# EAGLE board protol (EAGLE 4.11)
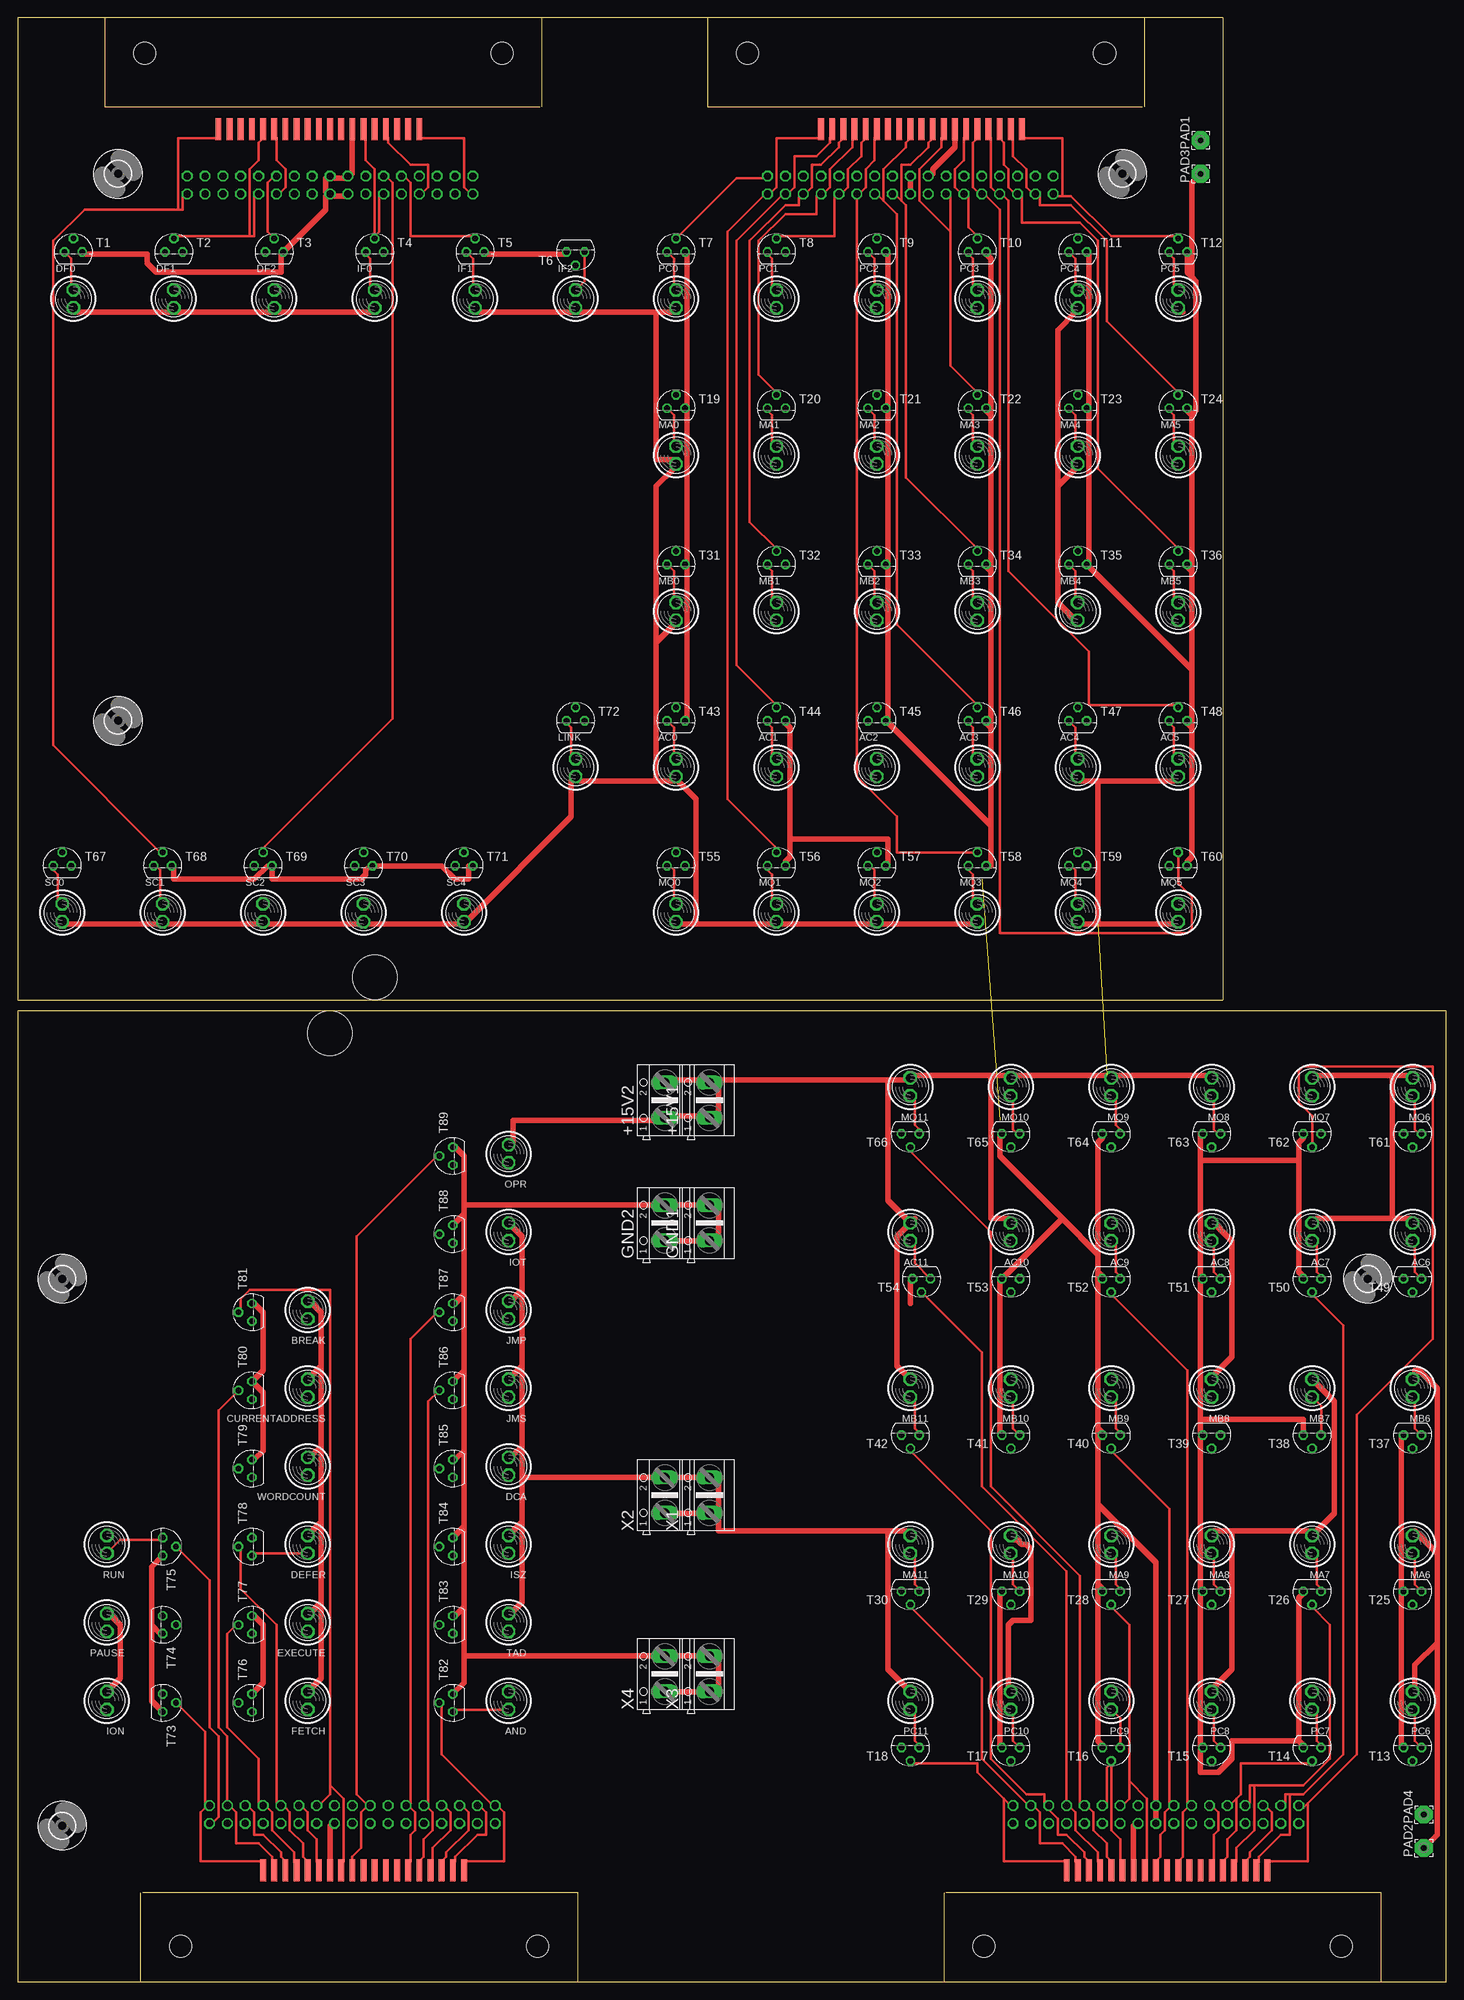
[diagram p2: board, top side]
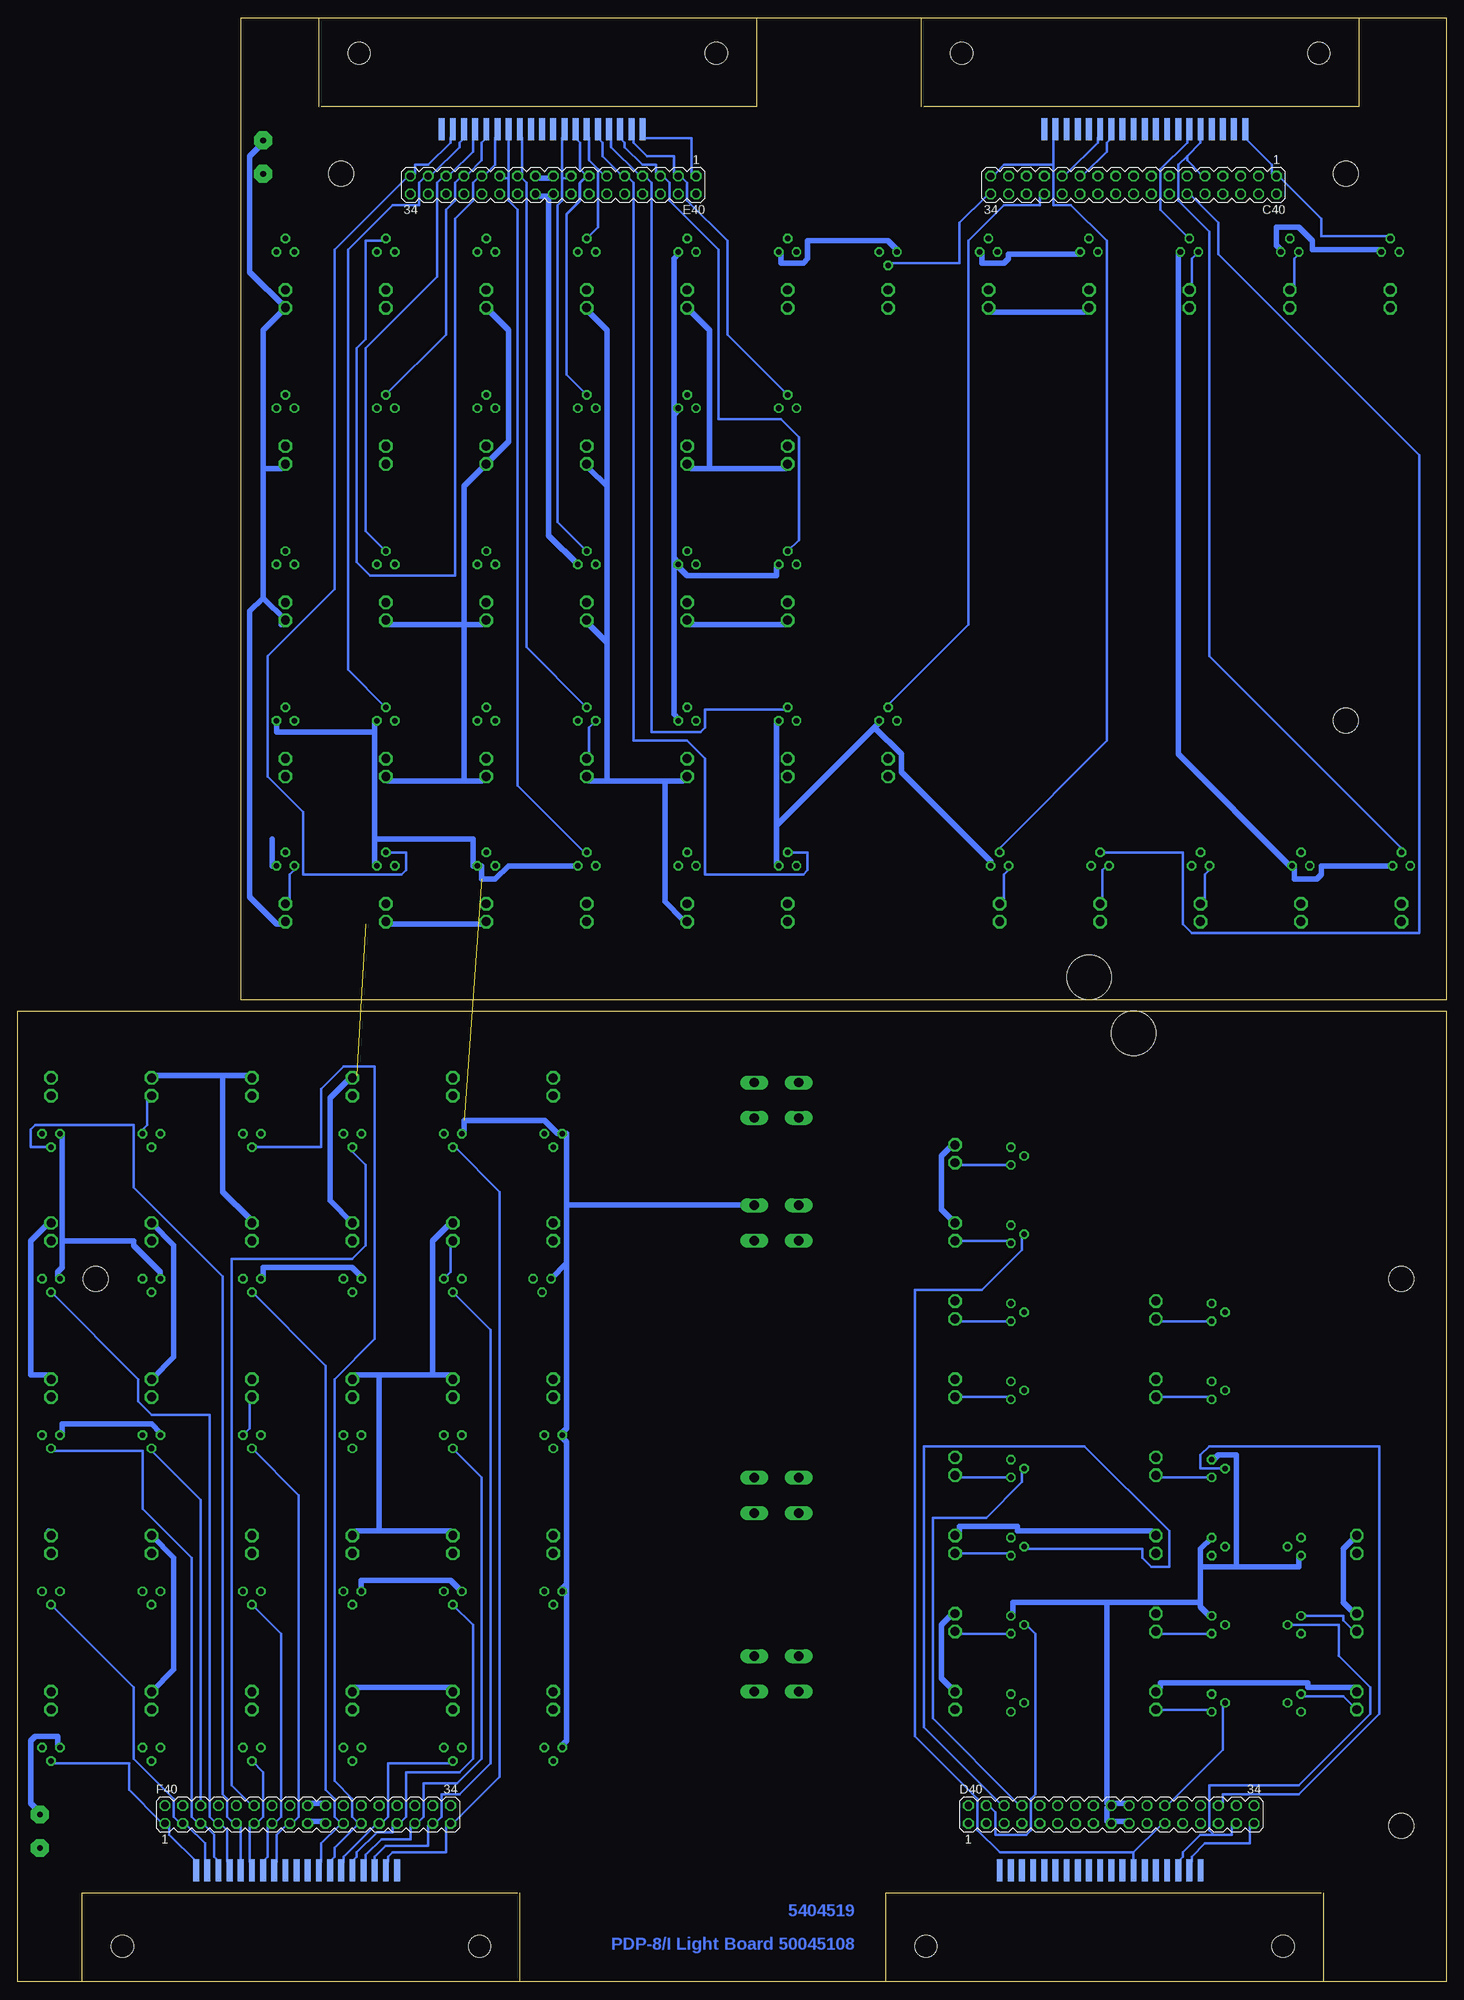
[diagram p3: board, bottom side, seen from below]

Size 203.2 x 279.4 mm. Coordinates in mm from the lower left corner, seen from the top.
Outline: 0,139.7 171.45,139.7 171.45,279.4 0,279.4 0,139.7
Outline: 203.2,138.11 0,138.11 0,0 203.2,0 203.2,138.11
Copper layers (1*16): Top 0.035mm / dielectric 1.5mm / Bottom 0.035mm
Design rules "15mils": minimum track width 15mil, minimum drill 24mil, track to track 15mil, track to pad 10mil, pad to pad 10mil, via to via 10mil, smd to smd 10mil, copper to edge 25mil, drill to drill 10mil, minimum pad ring 10mil, minimum via ring 8mil, stop-mask expansion 0mil, vias tented up to drill 0mil, thermal gap 10mil
Net classes: 1 supply: width 0.762 mm
Holes 6.35 mm at 50.8,142.88 44.45,134.94

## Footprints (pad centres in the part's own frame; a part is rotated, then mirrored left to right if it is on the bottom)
AK500/2 = drill 1.321 long: 1 -2.515,0; 2 2.515,0
BULB = drill 1.27 octagon: A 0,0; B 0,2.54
MA17-2 = drill 1.016 octagon: 1 -20.32,-1.27; 2 -20.32,1.27; 3 -17.78,-1.27; 4 -17.78,1.27; 5 -15.24,-1.27; 6 -15.24,1.27; 7 -12.7,-1.27; 8 -12.7,1.27; 9 -10.16,-1.27; 10 -10.16,1.27; 11 -7.62,-1.27; 12 -7.62,1.27; 13 -5.08,-1.27; 14 -5.08,1.27; 15 -2.54,-1.27; 16 -2.54,1.27; 17 0,-1.27; 18 0,1.27; 19 2.54,-1.27; 20 2.54,1.27; 21 5.08,-1.27; 22 5.08,1.27; 23 7.62,-1.27; 24 7.62,1.27; 25 10.16,-1.27; 26 10.16,1.27; 27 12.7,-1.27; 28 12.7,1.27; 29 15.24,-1.27; 30 15.24,1.27; 31 17.78,-1.27; 32 17.78,1.27; 33 20.32,-1.27; 34 20.32,1.27
FLEX19 = smd 3.175 x 0.838: 1 0,14.287; 2 0,12.7; 3 0,11.113; 4 0,9.525; 5 0,7.938; 6 0,6.35; 7 0,4.763; 8 0,3.175; 9 0,1.587; 10 0,0; 11 0,-1.587; 12 0,-3.175; 13 0,-4.763; 14 0,-6.35; 15 0,-7.938; 16 0,-9.525; 17 0,-11.113; 18 0,-12.7; 19 0,-14.287
2,54/0,8 = drill 0.813 pad 2.54 octagon: 1 0,0
TO92 = drill 0.813 octagon: 1 1.27,0; 2 0,1.905; 3 -1.27,0
STRAIN-RELIEF = hole 3.175: 7.62,56.515; 7.62,5.715
3,6 = hole 3.6: 0,0

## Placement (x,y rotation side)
+15V1  494864  [AK500/2]  98.42,125.41 90 top
+15V2  494864  [AK500/2]  92.08,125.41 90 top
AC0  [BULB]  93.66,171.45 0 top
AC1  [BULB]  107.95,171.45 0 top
AC2  [BULB]  122.24,171.45 0 top
AC3  [BULB]  136.53,171.45 0 top
AC4  [BULB]  150.81,171.45 0 top
AC5  [BULB]  165.1,171.45 0 top
AC6  [BULB]  198.44,107.95 180 top
AC7  [BULB]  184.15,107.95 180 top
AC8  [BULB]  169.86,107.95 180 top
AC9  [BULB]  155.57,107.95 180 top
AC10  [BULB]  141.29,107.95 180 top
AC11  [BULB]  127,107.95 180 top
AND  [BULB]  69.85,41.27 180 top
BREAK  [BULB]  41.27,96.84 180 top
C40  [MA17-2]  44.45,255.59 180 bottom
C40BOT  FLEX19  [FLEX19]  42.86,263.52 90 top
C40TOP  FLEX19  [FLEX19]  42.86,263.52 270 bottom
CURRENTADDRESS  [BULB]  41.27,85.72 180 top
D40  [MA17-2]  47.62,23.81 0 bottom
D40BOT  FLEX19  [FLEX19]  128.59,263.52 90 top
D40TOP  FLEX19  [FLEX19]  128.59,263.52 270 bottom
DCA  [BULB]  69.85,74.61 180 top
DEFER  [BULB]  41.27,63.5 180 top
DF0  [BULB]  7.94,238.12 0 top
DF1  [BULB]  22.23,238.12 0 top
DF2  [BULB]  36.51,238.12 0 top
E40  [MA17-2]  127,255.59 180 bottom
E40BOT  FLEX19  [FLEX19]  163.51,15.88 270 top
E40TOP  FLEX19  [FLEX19]  163.51,15.88 90 bottom
EXECUTE  [BULB]  41.27,52.39 180 top
F40  [MA17-2]  161.93,23.81 0 bottom
F40BOT  FLEX19  [FLEX19]  49.21,15.88 270 top
F40TOP  FLEX19  [FLEX19]  49.21,15.88 90 bottom
FETCH  [BULB]  41.27,41.27 180 top
GND1  494864  [AK500/2]  98.42,107.95 90 top
GND2  494864  [AK500/2]  92.08,107.95 90 top
IF0  [BULB]  50.8,238.12 0 top
IF1  [BULB]  65.09,238.12 0 top
IF2  [BULB]  79.38,238.12 0 top
ION  [BULB]  12.7,41.27 180 top
IOT  [BULB]  69.85,107.95 180 top
ISZ  [BULB]  69.85,63.5 180 top
JMP  [BULB]  69.85,96.84 180 top
JMS  [BULB]  69.85,85.72 180 top
LINK  [BULB]  79.38,171.45 0 top
MA0  [BULB]  93.66,215.9 0 top
MA1  [BULB]  107.95,215.9 0 top
MA2  [BULB]  122.24,215.9 0 top
MA3  [BULB]  136.53,215.9 0 top
MA4  [BULB]  150.81,215.9 0 top
MA5  [BULB]  165.1,215.9 0 top
MA6  [BULB]  198.44,63.5 180 top
MA7  [BULB]  184.15,63.5 180 top
MA8  [BULB]  169.86,63.5 180 top
MA9  [BULB]  155.57,63.5 180 top
MA10  [BULB]  141.29,63.5 180 top
MA11  [BULB]  127,63.5 180 top
MB0  [BULB]  93.66,193.68 0 top
MB1  [BULB]  107.95,193.68 0 top
MB2  [BULB]  122.24,193.68 0 top
MB3  [BULB]  136.53,193.68 0 top
MB4  [BULB]  150.81,193.68 0 top
MB5  [BULB]  165.1,193.68 0 top
MB6  [BULB]  198.44,85.72 180 top
MB7  [BULB]  184.15,85.72 180 top
MB8  [BULB]  169.86,85.72 180 top
MB9  [BULB]  155.57,85.72 180 top
MB10  [BULB]  141.29,85.72 180 top
MB11  [BULB]  127,85.72 180 top
MQ0  [BULB]  93.66,150.81 0 top
MQ1  [BULB]  107.95,150.81 0 top
MQ2  [BULB]  122.24,150.81 0 top
MQ3  [BULB]  136.53,150.81 0 top
MQ4  [BULB]  150.81,150.81 0 top
MQ5  [BULB]  165.1,150.81 0 top
MQ6  [BULB]  198.44,128.59 180 top
MQ7  [BULB]  184.15,128.59 180 top
MQ8  [BULB]  169.86,128.59 180 top
MQ9  [BULB]  155.57,128.59 180 top
MQ10  [BULB]  141.29,128.59 180 top
MQ11  [BULB]  127,128.59 180 top
OPR  [BULB]  69.85,119.06 180 top
PAD1  [2,54/0,8]  168.28,261.94 90 top
PAD2  [2,54/0,8]  200.03,19.05 90 top
PAD3  [2,54/0,8]  168.28,257.18 90 top
PAD4  [2,54/0,8]  200.03,23.81 90 top
PAUSE  [BULB]  12.7,52.39 180 top
PC0  [BULB]  93.66,238.12 0 top
PC1  [BULB]  107.95,238.12 0 top
PC2  [BULB]  122.24,238.12 0 top
PC3  [BULB]  136.53,238.12 0 top
PC4  [BULB]  150.81,238.12 0 top
PC5  [BULB]  165.1,238.12 0 top
PC6  [BULB]  198.44,41.27 180 top
PC7  [BULB]  184.15,41.27 180 top
PC8  [BULB]  169.86,41.27 180 top
PC9  [BULB]  155.57,41.27 180 top
PC10  [BULB]  141.29,41.27 180 top
PC11  [BULB]  127,41.27 180 top
RUN  [BULB]  12.7,63.5 180 top
SC0  [BULB]  6.35,150.81 0 top
SC1  [BULB]  20.64,150.81 0 top
SC2  [BULB]  34.92,150.81 0 top
SC3  [BULB]  49.21,150.81 0 top
SC4  [BULB]  63.5,150.81 0 top
T1  2N2222  [TO92]  7.94,246.06 0 top
T2  2N2222  [TO92]  22.23,246.06 0 top
T3  2N2222  [TO92]  36.51,246.06 0 top
T4  2N2222  [TO92]  50.8,246.06 0 top
T5  2N2222  [TO92]  65.09,246.06 0 top
T6  2N2222  [TO92]  79.38,246.06 180 top
T7  2N2222  [TO92]  93.66,246.06 0 top
T8  2N2222  [TO92]  107.95,246.06 0 top
T9  2N2222  [TO92]  122.24,246.06 0 top
T10  2N2222  [TO92]  136.53,246.06 0 top
T11  2N2222  [TO92]  150.81,246.06 0 top
T12  2N2222  [TO92]  165.1,246.06 0 top
T13  2N2222  [TO92]  198.44,33.34 180 top
T14  2N2222  [TO92]  184.15,33.34 180 top
T15  2N2222  [TO92]  169.86,33.34 180 top
T16  2N2222  [TO92]  155.57,33.34 180 top
T17  2N2222  [TO92]  141.29,33.34 180 top
T18  2N2222  [TO92]  127,33.34 180 top
T19  2N2222  [TO92]  93.66,223.84 0 top
T20  2N2222  [TO92]  107.95,223.84 0 top
T21  2N2222  [TO92]  122.24,223.84 0 top
T22  2N2222  [TO92]  136.53,223.84 0 top
T23  2N2222  [TO92]  150.81,223.84 0 top
T24  2N2222  [TO92]  165.1,223.84 0 top
T25  2N2222  [TO92]  198.44,55.56 180 top
T26  2N2222  [TO92]  184.15,55.56 180 top
T27  2N2222  [TO92]  169.86,55.56 180 top
T28  2N2222  [TO92]  155.57,55.56 180 top
T29  2N2222  [TO92]  141.29,55.56 180 top
T30  2N2222  [TO92]  127,55.56 180 top
T31  2N2222  [TO92]  93.66,201.61 0 top
T32  2N2222  [TO92]  107.95,201.61 0 top
T33  2N2222  [TO92]  122.24,201.61 0 top
T34  2N2222  [TO92]  136.53,201.61 0 top
T35  2N2222  [TO92]  150.81,201.61 0 top
T36  2N2222  [TO92]  165.1,201.61 0 top
T37  2N2222  [TO92]  198.44,77.79 180 top
T38  2N2222  [TO92]  184.15,77.79 180 top
T39  2N2222  [TO92]  169.86,77.79 180 top
T40  2N2222  [TO92]  155.57,77.79 180 top
T41  2N2222  [TO92]  141.29,77.79 180 top
T42  2N2222  [TO92]  127,77.79 180 top
T43  2N2222  [TO92]  93.66,179.39 0 top
T44  2N2222  [TO92]  107.95,179.39 0 top
T45  2N2222  [TO92]  122.24,179.39 0 top
T46  2N2222  [TO92]  136.53,179.39 0 top
T47  2N2222  [TO92]  150.81,179.39 0 top
T48  2N2222  [TO92]  165.1,179.39 0 top
T49  2N2222  [TO92]  198.44,100.01 180 top
T50  2N2222  [TO92]  184.15,100.01 180 top
T51  2N2222  [TO92]  169.86,100.01 180 top
T52  2N2222  [TO92]  155.57,100.01 180 top
T53  2N2222  [TO92]  141.29,100.01 180 top
T54  2N2222  [TO92]  128.59,100.01 180 top
T55  2N2222  [TO92]  93.66,158.75 0 top
T56  2N2222  [TO92]  107.95,158.75 0 top
T57  2N2222  [TO92]  122.24,158.75 0 top
T58  2N2222  [TO92]  136.53,158.75 0 top
T59  2N2222  [TO92]  150.81,158.75 0 top
T60  2N2222  [TO92]  165.1,158.75 0 top
T61  2N2222  [TO92]  198.44,120.65 180 top
T62  2N2222  [TO92]  184.15,120.65 180 top
T63  2N2222  [TO92]  169.86,120.65 180 top
T64  2N2222  [TO92]  155.57,120.65 180 top
T65  2N2222  [TO92]  141.29,120.65 180 top
T66  2N2222  [TO92]  127,120.65 180 top
T67  2N2222  [TO92]  6.35,158.75 0 top
T68  2N2222  [TO92]  20.64,158.75 0 top
T69  2N2222  [TO92]  34.92,158.75 0 top
T70  2N2222  [TO92]  49.21,158.75 0 top
T71  2N2222  [TO92]  63.5,158.75 0 top
T72  2N2222  [TO92]  79.38,179.39 0 top
T73  2N2222  [TO92]  20.64,39.69 270 top
T74  2N2222  [TO92]  20.64,50.8 270 top
T75  2N2222  [TO92]  20.64,61.91 270 top
T76  2N2222  [TO92]  33.34,39.69 90 top
T77  2N2222  [TO92]  33.34,50.8 90 top
T78  2N2222  [TO92]  33.34,61.91 90 top
T79  2N2222  [TO92]  33.34,73.03 90 top
T80  2N2222  [TO92]  33.34,84.14 90 top
T81  2N2222  [TO92]  33.34,95.25 90 top
T82  2N2222  [TO92]  61.91,39.69 90 top
T83  2N2222  [TO92]  61.91,50.8 90 top
T84  2N2222  [TO92]  61.91,61.91 90 top
T85  2N2222  [TO92]  61.91,73.03 90 top
T86  2N2222  [TO92]  61.91,84.14 90 top
T87  2N2222  [TO92]  61.91,95.25 90 top
T88  2N2222  [TO92]  61.91,106.36 90 top
T89  2N2222  [TO92]  61.91,117.47 90 top
TAD  [BULB]  69.85,52.39 180 top
U$1  [STRAIN-RELIEF]  74.61,266.7 90 top
U$2  [STRAIN-RELIEF]  160.34,266.7 90 top
U$3  [STRAIN-RELIEF]  131.76,12.7 270 top
U$4  [STRAIN-RELIEF]  17.46,12.7 270 top
U$5  [3,6]  6.35,22.23 180 top
U$6  [3,6]  6.35,100.01 180 top
U$7  [3,6]  192.09,100.01 180 top
U$8  [3,6]  14.29,179.39 0 top
U$9  [3,6]  14.29,257.18 0 top
U$11  [3,6]  157.16,257.18 0 top
WORDCOUNT  [BULB]  41.27,74.61 180 top
X1  494864  [AK500/2]  98.42,69.22 90 top
X2  494864  [AK500/2]  92.08,69.22 90 top
X3  494864  [AK500/2]  98.42,43.81 90 top
X4  494864  [AK500/2]  92.08,43.81 90 top

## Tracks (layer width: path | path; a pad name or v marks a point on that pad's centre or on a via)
+15V  (1 unrouted)
  Top 0.762: ION.A 14.61,43.18 14.61,50.8 13.34,52.07 PAUSE.A | 43.18,87.63 43.18,95.25 41.91,96.52 BREAK.A | 43.18,87.63 CURRENTADDRESS.A | 43.18,76.2 41.91,74.93 WORDCOUNT.A | 43.18,76.2 43.18,87.63 | 43.18,65.41 43.18,76.2 | DEFER.A 43.18,65.41 | 43.18,53.98 41.91,52.7 EXECUTE.A | 43.18,65.41 43.18,53.98 | 43.18,53.98 43.18,43.18 FETCH.A | X1.1 96.52,66.67 93.98,66.67 X2.1 | X1.1 99.69,67.31 99.69,71.12 X1.2 96.52,71.75 93.98,71.75 X2.2 90.17,71.75 71.75,71.75 | +15V1.2 96.52,128.27 93.98,128.27 +15V2.2 | +15V1.2 99.69,127 99.69,123.83 +15V1.1 96.52,123.19 93.98,123.19 +15V2.1 90.17,122.56 70.48,122.56 70.48,119.38 OPR.A | 71.75,98.42 70.48,97.16 JMP.A | 71.75,98.42 71.75,106.05 IOT.A | 71.75,98.42 71.75,87.63 | 71.75,87.63 JMS.A | 71.75,76.2 70.48,74.93 DCA.A | 71.75,87.63 71.75,76.2 | 71.75,76.2 71.75,71.75 | 71.75,71.75 71.75,65.41 | 71.75,65.41 ISZ.A | 71.75,65.41 71.75,53.98 70.48,52.7 TAD.A | 123.83,64.14 99.69,64.14 99.69,66.04 X1.1 | 123.83,64.14 126.36,64.14 MA11.A | DF0.A 8.26,237.49 21.59,237.49 DF1.A 22.86,237.49 36.2,237.49 DF2.A 36.83,237.49 50.16,237.49 IF0.A | IF1.A 65.41,237.49 78.74,237.49 IF2.A 80.01,237.49 90.81,237.49 | 90.81,237.49 93.34,237.49 PC0.A | 90.81,237.49 90.81,216.53 93.34,216.53 MA0.A 93.34,215.26 90.81,212.72 90.81,190.5 | PC5.A 165.74,237.49 | 172.72,64.14 170.18,64.14 MA8.A | 172.72,64.14 183.51,64.14 MA7.A 187.32,66.67 187.32,82.55 MB7.A | 172.72,64.14 172.72,44.45 170.18,41.91 PC8.A | 195.58,108.58 184.78,108.58 AC7.A | 195.58,108.58 198.12,108.58 AC6.A | 147.96,212.72 150.5,215.26 MA4.A | 147.96,212.72 147.96,196.22 150.5,193.68 MB4.A | 147.96,212.72 147.96,234.95 150.5,237.49 PC4.A
  Top 0.762: SC0.A 6.99,150.5 20.32,150.5 SC1.A 20.95,150.5 34.29,150.5 SC2.A 35.56,150.5 48.9,150.5 SC3.A 49.53,150.5 62.87,150.5 SC4.A 64.14,151.13 78.74,165.74 78.74,170.81 LINK.A 80.01,170.81 90.81,170.81 | AC10.A 140.97,108.58 138.43,108.58 138.43,128.91 | AC11.A 127.64,108.58 | MB11.A 125.09,87.63 125.09,106.05 AC11.A | 153.67,170.81 151.13,170.81 AC4.A | 153.67,170.81 164.47,170.81 AC5.A | 90.81,170.81 93.34,170.81 AC0.A 93.98,170.81 96.52,168.28 96.52,150.5 | 96.52,150.5 107.31,150.5 MQ1.A 108.58,150.5 121.92,150.5 MQ2.A 122.56,150.5 135.89,150.5 MQ3.A | 96.52,150.5 93.98,150.5 MQ0.A | 153.67,150.5 151.13,150.5 MQ4.A | 153.67,150.5 164.47,150.5 MQ5.A | 195.58,128.91 198.12,128.91 MQ6.A | 195.58,128.91 184.78,128.91 MQ7.A | MB8.A 170.18,86.36 172.72,88.9 172.72,105.41 170.18,107.95 AC8.A | MQ8.A 169.54,128.91 156.21,128.91 MQ9.A 154.94,128.91 141.6,128.91 MQ10.A 140.97,128.91 138.43,128.91 | 138.43,128.91 127.64,128.91 MQ11.A 126.36,128.27 123.83,128.27 | 90.81,190.5 93.34,193.04 MB0.A | 90.81,170.81 90.81,190.5 | 153.67,150.5 153.67,170.81 | 195.58,128.91 195.58,108.58 | 123.83,128.27 100.33,128.27 +15V1.2 | 123.83,64.14 123.83,44.45 PC11.A | 123.83,128.27 123.83,111.12 AC11.A | PC10.A 140.97,41.91 140.97,50.8 141.6,51.44 144.15,51.44 144.15,61.59 143.51,62.23 142.88,62.23 142.24,62.87 141.6,62.87 MA10.A | 201.93,48.26 198.75,45.09 198.75,41.91 PC6.A | 201.93,60.96 201.93,48.26 | 201.93,60.96 198.75,64.14 MA6.A | 201.93,60.96 201.93,84.45 199.39,87 198.75,87 198.75,86.36 MB6.A | 201.93,48.26 201.93,20.95 PAD2.1
  Bottom 0.762: RUN.A 14.61,61.59 14.61,53.98 13.34,52.7 PAUSE.A | ION.A 13.34,41.91 19.68,41.91 19.68,42.55 40.64,42.55 40.64,41.91 FETCH.A | 144.15,86.36 151.76,86.36 | 151.76,86.36 154.94,86.36 MB9.A | 144.15,86.36 141.6,86.36 MB10.A | OPR.A 70.48,118.75 71.75,117.47 71.75,109.86 IOT.A | AND.A 71.75,43.18 71.75,50.8 70.48,52.07 TAD.A | DEFER.A 41.91,64.14 60.96,64.14 60.96,64.77 69.22,64.77 69.22,64.14 ISZ.A | 104.78,215.26 107.31,215.26 MA1.A | 104.78,215.26 93.98,215.26 MA0.A | 104.78,215.26 104.78,234.95 PC1.A | IF1.A 64.77,237.49 51.44,237.49 IF0.A | 165.74,193.04 MB5.A 168.28,196.85 | MB6.A 198.75,86.36 201.29,86.36 201.29,105.41 198.75,107.95 AC6.A | 168.28,215.26 165.74,215.26 MA5.A | MA6.A 198.75,64.14 | 168.28,196.85 168.28,215.26 | 168.28,215.26 168.28,234.95 PC5.A 170.18,243.21 170.18,259.71 168.91,260.99 PAD1.1 | PC7.A 180.97,44.45 180.97,60.33 MA7.A | MB7.A 180.97,88.9 180.97,104.78 AC7.A | 119.38,170.81 121.92,170.81 AC2.A | 111.12,170.81 119.38,170.81 | 111.12,170.81 108.58,170.81 AC1.A | 119.38,190.5 121.92,193.04 MB2.A | 119.38,170.81 119.38,190.5 | 119.38,212.72 121.92,215.26 MA2.A | 119.38,190.5 119.38,212.72 | 119.38,212.72 119.38,234.95 121.92,237.49 PC2.A | 139.7,193.04 150.5,193.04 MB4.A | 139.7,193.04 137.16,193.04 MB3.A | 139.7,193.04 139.7,212.72 MA3.A 133.35,219.07 133.35,234.95 PC3.A | 139.7,170.81 150.5,170.81 AC4.A | 139.7,170.81 137.16,170.81 AC3.A | MB0.A 93.98,193.04 107.31,193.04 MB1.A | MQ4.A 150.5,150.5 137.16,150.5 MQ3.A | MQ6.A 198.75,128.91 | 173.99,128.91 183.51,128.91 MQ7.A | 173.99,128.91 170.18,128.91 MQ8.A | 173.99,128.91 173.99,112.39 170.18,108.58 AC8.A | AC9.A 158.75,111.12 158.75,125.73 156.21,128.27 MQ9.A
  Bottom 0.762: 139.7,170.81 139.7,193.04 | 111.12,170.81 111.12,153.67 108.58,151.13 MQ1.A | 144.15,86.36 144.15,105.41 141.6,107.95 AC10.A | PC9.A 154.94,41.91 141.6,41.91 PC10.A | 151.76,64.14 154.94,64.14 MA9.A | 151.76,86.36 151.76,64.14 | 151.76,64.14 141.6,64.14 MA10.A | 168.28,196.85 170.18,194.94 170.18,154.31 166.37,150.5 165.74,150.5 MQ5.A
AC0
  Bottom 0.381: T43.2 93.98,180.97 105.41,180.97 105.41,178.44 106.05,177.8 113.03,177.8 113.03,255.91 113.67,256.54 E40.7 114.94,257.18 118.75,260.99 118.75,262.25 D40TOP.4
AC1
  Top 0.381: T44.2 107.95,181.61 102.23,187.32 102.23,247.65 108.58,254 E40.4 109.86,254.63 110.49,255.27 110.49,259.71 113.67,259.71 115.57,261.62 115.57,262.25 D40BOT.2
AC2
  Bottom 0.381: T45.2 130.81,189.87 130.81,255.91 131.44,256.54 E40.21 131.44,257.18 131.44,262.25 D40TOP.12
AC3
  Top 0.381: 123.19,253.37 122.56,254 E40.14 | 123.19,253.37 125.09,251.46 125.09,193.04 136.53,181.61 T46.2 | 123.19,253.37 123.19,257.81 126.36,260.99 126.36,261.62 127,262.25 D40BOT.9
AC4
  Bottom 0.381: T47.2 156.21,186.69 156.21,246.38 149.86,252.73 146.05,252.73 146.05,255.91 145.41,256.54 E40.31 144.15,257.18 140.34,260.99 140.34,261.62 139.7,262.25 D40TOP.17
AC5
  Top 0.381: T48.2 165.1,181.61 152.4,181.61 152.4,189.23 140.97,200.66 140.97,253.37 140.34,254 E40.28 139.06,254.63 138.43,255.27 138.43,262.25 D40BOT.16
AC6
  Bottom 0.381: T49.2 186.06,85.72 186.06,82.55 184.15,80.64 175.9,80.64 175.9,23.5 175.26,22.86 F40.7 173.99,22.23 173.35,21.59 173.35,17.14 E40TOP.4
AC7
  Top 0.381: 180.97,26.67 180.34,26.67 180.34,25.4 F40.4 | 180.97,26.67 182.88,26.67 188.59,32.38 188.59,93.34 184.15,97.79 T50.2 | 180.97,26.67 180.97,20.95 179.71,20.95 176.53,17.78 176.53,17.14 E40BOT.2
AC8
  Bottom 0.381: T51.2 159.38,87.63 159.38,27.3 158.12,26.04 158.12,23.5 157.48,22.86 F40.21 157.48,22.23 160.02,19.68 160.02,17.14 E40TOP.12
AC9
  Top 0.381: T52.2 155.57,97.79 166.37,87 166.37,25.4 F40.14 166.37,24.77 165.74,24.13 165.74,17.78 165.1,17.14 E40BOT.9
AC10
  Bottom 0.381: T53.2 135.89,92.71 135.89,31.11 140.34,26.67 142.88,26.67 142.88,23.5 143.51,22.86 F40.31 144.78,22.23 144.78,19.37 150.81,19.37 152.4,17.78 E40TOP.17
AC11
  Top 0.381: T54.2 137.16,89.53 137.16,70.48 149.22,58.42 F40.28 149.86,24.77 150.5,24.13 150.5,21.59 153.67,18.41 153.67,17.14 E40BOT.16
AND
  Top 0.381: T82.2 60.33,39.37 60.33,32.38 67.31,25.4 D40.2 68.58,24.77 69.22,24.13 69.22,17.14 63.5,17.14 F40BOT.1
BREAK
  Top 0.381: 44.45,27.94 44.45,26.67 43.18,25.4 D40.22 | 44.45,27.94 44.45,98.42 33.02,98.42 31.75,97.16 31.75,95.25 T81.2 | 44.45,27.94 46.35,26.04 46.35,17.14 F40BOT.12
CA
  Top 0.381: T80.2 28.57,81.28 28.57,36.2 29.84,34.92 D40.32 30.48,24.77 31.11,24.13 31.11,19.68 34.29,19.68 36.2,17.78 36.2,17.14 F40BOT.18
DCA
  Top 0.381: F40BOT.4 59.05,17.14 59.05,19.05 61.59,21.59 61.59,24.13 60.96,24.77 D40.8
  Bottom 0.381: T85.2 60.33,73.03 60.33,71.12 65.41,66.04 73.03,66.04 73.03,37.47 60.96,25.4 D40.8
DEFER
  Top 0.381: T78.2 31.75,61.59 31.75,55.88 36.83,50.8 36.83,25.4 D40.26 38.1,24.77 38.73,24.13 38.73,21.59 40.64,19.68 40.64,17.78 41.27,17.14 F40BOT.15
DF0
  Bottom 0.381: T1.2 8.26,248.28 17.78,248.28 17.78,250.82 23.5,256.54 C40.1 24.77,257.18 24.77,258.44 28.57,262.25 C40TOP.1
DF1
  Top 0.381: 33.02,248.28 33.66,248.28 33.66,254 C40.10 | 33.02,248.28 22.23,248.28 T2.2 | 33.02,248.28 33.02,257.81 34.29,259.08 34.29,261.62 34.92,262.25 C40BOT.5
DF2
  Top 0.381: T3.2 35.56,248.92 35.56,255.91 36.2,256.54 C40.11
  Bottom 0.381: C40TOP.6 36.83,262.25 36.83,261.62 40.64,257.81 40.64,252.09 T3.2
EXECUTE
  Top 0.381: T77.2 31.11,50.8 29.84,49.53 29.84,36.2 34.29,31.75 34.29,25.4 D40.28 35.56,24.77 36.2,24.13 36.2,21.59 39.37,18.41 39.37,17.14 F40BOT.16
FETCH
  Top 0.381: F40BOT.14 42.55,17.14 42.55,20.32 41.27,21.59 41.27,24.13 40.64,24.77 D40.24
  Bottom 0.381: T76.2 31.75,39.37 31.75,33.02 39.37,25.4 D40.24
GND  (1 unrouted)
  Top 0.762: T76.1 34.92,42.55 34.92,50.8 33.66,52.07 T77.1 | 19.05,50.8 19.05,59.05 T75.1 | 19.05,50.8 20.32,49.53 T74.1 | 19.05,50.8 19.05,40.01 T73.1 | 63.5,110.49 63.5,117.47 62.23,118.75 T89.1 | 63.5,110.49 63.5,109.22 | 63.5,109.22 T88.1 | 63.5,97.79 62.23,96.52 T87.1 | 63.5,109.22 63.5,97.79 | 63.5,97.79 63.5,87 | 63.5,87 T86.1 | 63.5,75.56 62.23,74.3 T85.1 | 63.5,87 63.5,75.56 | 63.5,75.56 63.5,64.77 | 63.5,64.77 T84.1 | 63.5,53.34 62.23,52.07 T83.1 | 63.5,64.77 63.5,53.34 | 63.5,53.34 63.5,46.35 | 63.5,46.35 63.5,42.55 T82.1 | T41.1 139.7,78.11 139.7,99.69 T53.1 148.59,108.58 | X4.1 93.98,41.27 96.52,41.27 X3.1 99.69,41.91 99.69,45.72 X3.2 96.52,46.35 93.98,46.35 X4.2 90.17,46.35 63.5,46.35 | GND2.1 93.98,105.41 96.52,105.41 GND1.1 99.69,106.05 99.69,109.86 GND1.2 96.52,110.49 93.98,110.49 GND2.2 90.17,110.49 63.5,110.49 | 153.67,103.5 153.67,100.97 | 153.67,103.5 153.67,119.38 154.31,120.02 T64.1 | 153.67,100.97 154.31,100.33 T52.1 | 153.67,78.74 154.31,78.11 T40.1 | 153.67,100.97 153.67,78.74 | 153.67,56.52 154.31,55.88 T28.1 | 153.67,78.74 153.67,67.94 | 153.67,67.94 153.67,56.52 | 148.59,108.58 153.67,103.5 | 148.59,108.58 139.7,117.47 139.7,120.65 T65.1 | 127,96.52 127,99.69 T54.1 | 182.25,34.29 182.25,54.61 182.88,55.24 T26.1 | 182.25,34.29 182.88,33.66 T14.1 | 182.25,116.84 182.25,100.97 182.88,100.33 T50.1 | 182.25,116.84 182.25,119.38 182.88,120.02 T62.1 | 168.28,116.84 168.28,100.33 T51.1 168.28,99.69 168.28,80.01 | 168.28,116.84 168.28,120.65 T63.1 | 168.28,80.01 168.28,78.11 T39.1 168.28,77.47 168.28,55.88 T27.1 168.28,55.24 168.28,33.66 T15.1 168.28,33.02 168.28,29.84 170.81,29.84 172.72,31.75 172.72,34.29 182.25,34.29
  Top 0.762: 168.28,116.84 182.25,116.84 | T37.1 196.85,77.47 196.85,55.88 T25.1 196.85,55.24 196.85,33.66 T13.1 | T11.1 152.4,245.75 152.4,224.16 T23.1 152.4,223.52 152.4,201.93 T35.1 167,186.69 | 167,178.44 167,160.02 166.37,159.38 T60.1 | 167,178.44 166.37,179.07 T48.1 | 167,200.66 166.37,201.29 T36.1 | 167,178.44 167,186.69 | 167,186.69 167,200.66 | 167,222.88 166.37,223.52 T24.1 | 167,200.66 167,222.88 | 168.28,80.01 182.88,80.01 T38.1 | 109.86,162.56 109.86,178.44 109.22,179.07 T44.1 | 109.86,162.56 109.86,160.02 109.22,159.38 T56.1 | 109.86,162.56 123.83,162.56 123.83,158.75 T57.1 | T9.1 123.83,245.75 123.83,224.16 T21.1 123.83,223.52 123.83,201.93 T33.1 123.83,201.29 123.83,179.71 T45.1 138.43,164.47 | T1.1 9.53,245.75 18.41,245.75 18.41,244.47 19.68,243.21 37.47,243.21 37.47,245.75 T3.1 43.81,252.09 43.81,254 C40.18 | T71.1 64.14,158.75 64.14,156.84 62.23,156.84 60.33,158.75 T70.1 50.16,158.75 49.53,158.12 49.53,157.48 48.9,156.84 36.2,156.84 T69.1 35.56,158.75 33.66,156.84 22.23,156.84 22.23,158.75 T68.1 | T6.1 78.11,245.75 66.67,245.75 T5.1 | T43.1 95.25,179.71 95.25,201.29 T31.1 95.25,201.93 95.25,223.52 T19.1 95.25,224.16 95.25,245.75 T7.1 | T29.1 139.7,55.24 139.7,33.66 T17.1 | C40.18 45.09,254 46.35,254 C40.20 | C40BOT.13 47.62,257.18 C40.19 46.35,256.54 45.09,256.54 C40.17 43.81,256.54 43.81,254.63 C40.18 | F40BOT.13 44.45,22.23 D40.19 | T81.1 33.66,96.52 34.92,95.25 34.92,87 T80.1 34.92,83.82 34.92,75.56 33.66,74.3 T79.1 | D40BOT.13 133.35,260.99 130.18,257.81 130.18,257.18 E40.19 | E40.18 E40.17 | 138.43,178.44 137.79,179.07 T46.1 | 138.43,164.47 138.43,158.75 T58.1
  Top 0.762: 138.43,164.47 138.43,178.44 | 138.43,200.66 137.79,201.29 T34.1 | 138.43,178.44 138.43,200.66 | 138.43,222.88 137.79,223.52 T22.1 | 138.43,200.66 138.43,222.88 | 138.43,222.88 138.43,245.11 137.79,245.75 T10.1 | E40BOT.13 158.75,22.23 F40.19 | F40.17 F40.18 161.93,59.69 153.67,67.94 | 153.67,56.52 153.67,34.29 154.31,33.66 T16.1 | 167,242.57 167.64,241.94 167.64,223.52 167,222.88 | 167,242.57 166.37,243.21 T12.1 | 167,242.57 167,255.91 PAD3.1
  Bottom 0.762: 34.92,53.98 34.92,53.34 33.66,52.07 T77.1 | 34.92,53.98 34.92,59.05 | 34.92,59.05 34.92,61.59 T78.1 | 29.84,59.05 20.95,59.05 20.95,60.33 T75.1 | 34.92,59.05 29.84,59.05 | 48.26,53.98 61.59,53.98 61.59,52.07 T83.1 | 48.26,53.98 34.92,53.98 | 29.84,59.05 29.84,74.93 32.38,74.93 33.02,74.3 T79.1 | T65.1 139.7,120.65 139.7,122.56 128.27,122.56 126.36,120.65 T66.1 125.09,120.65 125.09,110.49 | T12.1 166.37,245.75 | T13.1 197.49,33.66 197.49,34.92 200.66,34.92 201.29,34.29 201.29,25.4 200.66,24.77 PAD4.1 | T38.1 182.88,78.11 184.15,79.38 196.85,79.38 196.85,78.11 T37.1 | 196.85,105.41 196.85,101.6 197.49,100.97 197.49,100.33 T49.1 | 196.85,105.41 196.85,120.65 T61.1 | 152.4,177.8 152.4,179.07 T47.1 | 152.4,162.56 152.4,177.8 | 152.4,162.56 152.4,158.75 T59.1 | 152.4,177.8 166.37,177.8 T48.1 | 167,162.56 167,158.75 T60.1 | T57.1 133.35,158.75 135.25,156.84 137.16,156.84 137.16,158.75 T58.1 138.43,158.75 138.43,162.56 152.4,162.56 | T1.1 9.53,246.38 19.05,246.38 19.05,247.65 20.95,249.56 24.13,249.56 24.13,247.01 23.5,246.38 T2.1 | T67.1 17.78,158.75 17.78,157.48 18.41,156.84 21.59,156.84 21.59,158.75 T68.1 22.23,158.75 38.1,174.62 38.1,245.75 T3.1 | T4.1 52.07,245.75 62.23,245.75 62.23,245.11 62.87,244.47 66.04,244.47 66.04,245.75 T5.1 | 95.25,164.47 95.25,179.07 T43.1 | 95.25,164.47 95.25,158.75 T55.1 | 81.28,178.44 95.25,164.47 | 81.28,178.44 80.64,179.07 T72.1 | T31.1 95.25,201.29 95.25,200.03 107.95,200.03 109.22,201.29 T32.1 109.22,201.93 109.86,202.56 | 109.86,222.88 109.22,223.52 T20.1 | 109.86,202.56 109.86,222.88 | 109.86,222.88 109.86,245.11 109.22,245.75 T8.1 | T6.1 78.11,246.38 79.38,247.65 90.81,247.65 90.81,245.11 91.44,244.47 94.61,244.47 94.61,245.75 T7.1
  Bottom 0.762: 81.28,178.44 77.47,174.62 77.47,172.09 64.77,159.38 T71.1 | 109.86,202.56 109.86,180.34 109.22,179.71 T44.1 | T52.1 154.31,100.33 155.57,101.6 168.28,101.6 168.28,100.33 T51.1 | 125.09,56.52 125.09,76.83 125.73,77.47 T42.1 125.73,78.11 125.09,78.74 125.09,102.23 | 125.09,56.52 125.73,55.88 T30.1 | 125.09,56.52 125.09,34.29 125.73,33.66 T18.1 | 125.09,110.49 125.09,102.23 | 125.09,102.23 T54.1 | 125.09,110.49 100.33,110.49 GND1.2 | D40.18 46.99,25.4 45.72,25.4 D40.20 | D40.19 45.72,22.86 46.99,22.86 D40.17 48.26,22.86 48.26,24.77 D40.18 | 48.26,53.98 48.26,25.4 D40.18 | 127.64,254 128.91,254 E40.20 | E40.17 127.64,256.54 128.91,256.54 E40.19 | 127.64,254 127.64,205.74 T33.1 | 127.64,254 E40.18 | F40.18 161.29,25.4 160.02,25.4 F40.20 | F40.17 161.29,22.86 160.02,22.86 F40.19 | T29.1 141.6,57.15 154.31,57.15 T28.1 | 196.85,105.41 186.69,105.41 186.69,104.78 182.88,100.97 T50.1
IF0
  Top 0.381: 50.8,248.28 51.44,248.92 51.44,254 C40.24 | 50.8,248.28 50.8,257.81 49.53,259.08 49.53,262.25 C40BOT.14 | T4.2 50.8,248.28
IF1
  Top 0.381: T5.2 64.77,248.28 55.88,248.28 55.88,255.91 55.24,256.54 C40.25
  Bottom 0.381: C40TOP.14 49.53,262.25 49.53,261.62 53.98,257.18 C40.25
IF2
  Top 0.381: C40BOT.19 57.15,262.25 63.5,262.25 63.5,255.27 64.14,254.63 C40.34
  Bottom 0.381: T6.2 79.38,244.47 69.22,244.47 69.22,250.19 65.41,254 C40.34
ION
  Top 0.381: T73.2 26.67,35.56 26.67,25.4 D40.34 26.67,24.77 26.04,24.13 26.04,17.14 34.92,17.14 F40BOT.19
IOT
  Bottom 0.381: 44.45,18.41 63.5,18.41 66.67,21.59 66.67,26.04 75.56,34.92 75.56,98.42 66.04,98.42 60.33,104.14 60.33,106.05 T88.2 | 44.45,18.41 F40TOP.13 | 44.45,18.41 40.64,22.23 D40.23
ISZ
  Top 0.381: F40BOT.3 60.33,17.14 60.96,17.78 60.96,18.41 64.14,21.59 64.14,24.13 63.5,24.77 D40.6
  Bottom 0.381: T84.2 59.69,61.59 43.18,61.59 43.18,60.33 41.91,59.05 39.37,59.05 39.37,64.14 51.44,76.2 74.3,76.2 74.3,36.2 63.5,25.4 D40.6
JMP
  Top 0.381: T87.2 59.69,95.25 55.88,91.44 55.88,25.4 D40.12 55.88,24.77 56.52,24.13 56.52,21.59 55.88,20.95 55.88,17.14 F40BOT.6
JMS
  Top 0.381: T86.2 58.42,82.55 58.42,25.4 D40.10 58.42,24.77 59.05,24.13 59.05,21.59 57.78,20.32 57.78,17.78 57.15,17.14 F40BOT.5
LINK
  Top 0.381: C40BOT.16 52.7,262.25 52.7,261.62 55.88,258.44 58.42,258.44 58.42,255.27 57.78,254.63 C40.28
  Bottom 0.381: T72.2 79.38,181.61 67.94,193.04 67.94,247.65 62.87,252.73 57.78,252.73 57.78,254 C40.28
MA0
  Bottom 0.381: T19.2 102.23,234.31 102.23,247.65 107.95,253.37 107.95,255.91 108.58,256.54 E40.3 109.86,257.18 109.86,259.71 113.67,259.71 115.57,261.62 115.57,262.25 D40TOP.2
MA1
  Top 0.381: T20.2 107.95,226.06 105.41,228.6 105.41,247.65 109.22,251.46 113.67,251.46 113.67,254 E40.8 114.94,254.63 115.57,255.27 115.57,257.81 118.75,260.99 118.75,262.25 D40BOT.4
MA2
  Bottom 0.381: D40TOP.7 123.83,262.25 123.19,261.62 123.19,257.81 122.56,257.18 E40.13 | 125.09,251.46 125.09,228.6 T21.2
  Bottom 0.406: E40.13 122.24,256.86 123.19,255.91 123.19,253.37 125.09,251.46
MA3
  Top 0.381: 132.72,248.92 132.72,254 E40.22 | 132.72,248.92 132.72,229.87 136.53,226.06 T22.2 | 132.72,248.92 128.27,253.37 128.27,257.81 131.44,260.99 131.44,262.25 D40BOT.12
MA4
  Bottom 0.381: T23.2 142.24,234.31 142.24,252.09 140.97,253.37 140.97,255.91 140.34,256.54 E40.27 139.06,257.18 137.16,259.08 137.16,261.62 136.53,262.25 D40TOP.15
MA5
  Top 0.381: T24.2 165.1,226.06 154.94,236.22 154.94,247.65 149.86,252.73 145.41,252.73 145.41,254 E40.32 144.15,254.63 143.51,255.27 143.51,257.81 141.6,259.71 141.6,262.25 D40BOT.18
MA6
  Bottom 0.381: T25.2 186.69,41.91 186.69,31.75 180.97,26.04 180.97,23.5 180.34,22.86 F40.3 179.07,22.23 176.53,19.68 176.53,17.14 E40TOP.2
MA7
  Top 0.381: 175.9,27.94 175.26,27.94 175.26,25.4 F40.8 | 175.9,27.94 182.88,27.94 186.69,31.75 186.69,50.8 184.15,53.34 T26.2 | 175.9,27.94 175.9,21.59 173.35,19.05 173.35,17.14 E40BOT.4
MA8
  Bottom 0.381: T27.2 165.74,49.53 165.74,23.5 166.37,22.86 F40.13 167.64,22.23 167.64,17.78 168.28,17.14 E40TOP.7
MA9
  Top 0.381: 158.12,28.57 158.12,26.04 157.48,25.4 F40.22 | 158.12,28.57 158.12,50.8 155.57,53.34 T28.2 | 158.12,28.57 160.66,26.04 160.66,17.14 E40BOT.12
MA10
  Bottom 0.381: E40TOP.15 155.57,17.14 154.94,17.78 154.94,18.41 152.08,21.27 149.86,21.27 149.86,22.23 F40.27 148.59,22.86 147.96,23.5 147.96,29.84 140.34,29.84 138.43,31.75 138.43,50.8 T29.2
MA11
  Top 0.381: E40BOT.18 150.5,17.14 150.5,17.78 148.59,19.68 145.41,19.68 145.41,24.13 144.78,24.77 F40.32 143.51,25.4 137.16,31.75 137.16,43.18 127,53.34 T30.2
MB0
  Bottom 0.381: T31.2 92.08,205.1 92.08,219.71 94.61,222.25 103.5,222.25 103.5,246.38 110.49,253.37 110.49,255.91 111.12,256.54 E40.5 112.39,257.18 112.39,258.44 114.3,258.44 116.84,260.99 116.84,261.62 117.47,262.25 D40TOP.3
MB1
  Top 0.381: T32.2 107.95,203.84 104.14,207.65 104.14,247.65 109.22,252.73 111.12,252.73 111.12,254 E40.6 112.39,254.63 113.03,255.27 113.03,258.44 114.3,258.44 116.84,260.99 116.84,261.62 117.47,262.25 D40BOT.3
MB2
  Bottom 0.381: 125.73,256.54 125.73,262.25 D40TOP.8 | 125.73,256.54 125.09,256.54 E40.15 | T33.2 126.36,207.65 126.36,252.73 125.73,253.37 125.73,256.54
MB3
  Top 0.381: 125.73,253.37 125.09,254 E40.16 | 125.73,253.37 126.36,252.73 126.36,214 136.53,203.84 T34.2 | 125.73,253.37 125.73,258.44 127,258.44 129.54,260.99 129.54,261.62 130.18,262.25 D40BOT.11
MB4
  Bottom 0.381: T35.2 153.67,206.38 153.67,232.41 143.51,242.57 143.51,255.91 142.88,256.54 E40.29 141.6,257.18 138.43,260.35 138.43,262.25 D40TOP.16
MB5
  Top 0.381: T36.2 165.1,203.84 153.67,215.26 153.67,247.65 151.13,250.19 142.88,250.19 142.88,254 E40.30 141.6,254.63 140.97,255.27 140.97,257.81 140.34,258.44 140.34,261.62 139.7,262.25 D40BOT.17
MB6
  Bottom 0.381: T37.2 198.12,75.56 185.42,75.56 185.42,67.31 178.44,60.33 178.44,23.5 177.8,22.86 F40.5 176.53,22.23 175.26,20.95 175.26,17.78 174.62,17.14 E40TOP.3
MB7
  Top 0.381: E40BOT.3 174.62,17.14 175.26,17.78 175.26,18.41 178.44,21.59 178.44,24.13 177.8,24.77 F40.6
  Bottom 0.381: T38.2 184.15,75.56 177.16,68.58 F40.6
MB8
  Bottom 0.381: T39.2 163.19,69.22 163.19,23.5 163.83,22.86 F40.15 165.1,22.23 166.37,20.95 166.37,17.14 E40TOP.8
MB9
  Top 0.381: T40.2 155.57,75.56 163.83,67.31 163.83,25.4 F40.16 163.83,24.77 163.19,24.13 163.19,21.59 162.56,20.95 162.56,17.78 161.93,17.14 E40BOT.11
MB10
  Bottom 0.381: E40TOP.16 153.67,17.14 153.67,18.1 151.45,20.32 147.32,20.32 147.32,22.23 F40.29 146.05,22.86 145.41,23.5 145.41,28.26 140.65,28.26 137.16,31.75 137.16,71.75 T41.2
MB11
  Top 0.381: E40BOT.17 152.4,17.14 151.76,17.78 151.76,18.41 149.22,20.95 147.96,20.95 147.96,23.18 146.69,24.45 F40.30 146.05,25.4 146.05,26.67 143.51,26.67 138.43,31.75 138.43,64.14 127,75.56 T42.2
MQ0
  Bottom 0.381: T55.2 90.81,160.66 90.81,158.12 91.44,157.48 105.41,157.48 105.41,173.99 107.95,176.53 115.57,176.53 115.57,255.91 116.2,256.54 E40.9 117.47,257.18 120.02,259.71 120.02,261.62 120.65,262.25 D40TOP.5
MQ1
  Top 0.381: T56.2 107.95,161.29 100.97,168.28 100.97,248.92 106.05,254 E40.2 107.31,254.63 107.95,255.27 107.95,262.25 114.3,262.25 D40BOT.1
MQ2
  Bottom 0.381: 133.35,256.54 133.35,253.37 132.08,252.09 132.08,170.18 122.56,160.66 T57.2 | 133.35,256.54 D40TOP.13 | 133.35,256.54 133.99,256.54 E40.23
MQ3
  Top 0.381: T58.2 125.09,160.66 125.09,165.74 119.38,171.45 E40.12 120.02,254.63 120.65,255.27 120.65,257.81 121.92,259.08 121.92,262.25 D40BOT.6
MQ4
  Bottom 0.381: T59.2 147.96,160.66 147.96,158.12 148.59,157.48 162.56,157.48 162.56,166.37 167.64,171.45 167.64,188.59 158.12,198.12 158.12,246.38 147.96,256.54 E40.33 146.69,257.18 146.69,258.44 144.78,258.44 141.6,261.62 141.6,262.25 D40TOP.18
MQ5
  Top 0.381: T60.2 165.1,156.21 167,154.31 167,149.86 166.37,149.22 139.7,149.22 139.7,252.09 137.79,254 E40.26 136.53,254.63 135.89,255.27 135.89,261.62 136.53,262.25 D40BOT.15
MQ6
  Bottom 0.381: T61.2 201.29,118.75 201.29,121.28 200.66,121.92 186.69,121.92 186.69,113.03 173.99,100.33 173.99,26.67 173.35,26.04 173.35,23.5 172.72,22.86 F40.9 171.45,22.23 E40TOP.5
MQ7
  Top 0.381: 183.51,25.4 182.88,24.77 F40.2 | 183.51,25.4 190.5,32.38 190.5,80.64 201.29,91.44 201.29,130.18 182.88,130.18 182.25,129.54 182.25,125.09 184.15,123.19 T62.2 | 183.51,25.4 183.51,17.14 177.8,17.14 E40BOT.1
MQ8
  Bottom 0.381: T63.2 160.02,118.75 160.02,127 156.84,130.18 152.4,130.18 152.4,91.44 158.12,85.72 158.12,28.57 155.57,26.04 155.57,23.5 154.94,22.86 F40.23 154.94,22.23 158.12,19.05 158.12,17.78 158.75,17.14 E40TOP.13
MQ9
  Top 0.381: E40BOT.6 170.18,17.14 170.18,20.95 170.81,21.59 170.81,24.13 170.18,24.77 F40.12
  Bottom 0.381: T64.2 155.57,118.11 153.67,116.2 153.67,104.78 155.57,102.87 172.72,102.87 172.72,27.94 170.18,25.4 F40.12
MQ10
  Bottom 0.381: T65.2 140.97,118.75 134.62,112.39 134.62,29.21 140.97,22.86 F40.33 142.24,22.23 142.24,18.41 149.86,18.41 150.5,17.78 150.5,17.14 E40TOP.18
MQ11
  Top 0.381: T66.2 127,118.11 138.43,106.68 138.43,70.48 151.13,57.78 151.13,25.4 F40.26 152.4,24.77 153.03,24.13 153.03,21.59 154.94,19.68 154.94,17.78 155.57,17.14 E40BOT.15
N$1
  Top 0.381: T1.3 7.62,245.11 7.62,241.3 DF0.B
N$2
  Bottom 0.381: T2.3 20.95,245.75 21.59,245.11 21.59,241.3 DF1.B
N$3
  Bottom 0.381: T3.3 36.2,245.11 36.2,241.3 DF2.B
N$4
  Top 0.381: T4.3 49.53,245.75 50.16,245.11 50.16,241.3 IF0.B
N$5
  Top 0.381: T5.3 64.77,245.11 64.77,241.3 IF1.B
N$6
  Top 0.381: T6.3 80.64,241.94 IF2.B
N$7
  Top 0.381: T7.3 93.34,245.11 93.34,241.3 PC0.B
N$8
  Top 0.381: T8.3 106.68,245.75 107.31,245.11 107.31,241.3 PC1.B
N$9
  Top 0.381: T9.3 121.92,245.11 121.92,241.3 PC2.B
N$10
  Top 0.381: T10.3 135.25,245.75 135.89,245.11 135.89,241.3 PC3.B
N$11
  Top 0.381: T11.3 150.5,245.11 150.5,241.3 PC4.B
N$12
  Top 0.381: T12.3 163.83,245.75 164.47,245.11 164.47,241.3 PC5.B
N$13
  Top 0.381: T13.3 198.75,34.29 198.75,38.1 PC6.B
N$14
  Top 0.381: T14.3 185.42,33.66 184.78,34.29 184.78,38.1 PC7.B
N$15
  Top 0.381: T15.3 170.18,34.29 170.18,38.1 PC8.B
N$16
  Top 0.381: T16.3 156.84,37.47 PC9.B
N$17
  Top 0.381: T17.3 141.6,34.29 141.6,38.1 PC10.B
N$18
  Top 0.381: T18.3 128.27,33.66 127.64,34.29 127.64,38.1 PC11.B
N$19
  Top 0.381: T19.3 93.34,222.88 93.34,219.07 MA0.B
N$20
  Top 0.381: T20.3 106.68,223.52 107.31,222.88 107.31,219.07 MA1.B
N$21
  Top 0.381: T21.3 121.92,222.88 121.92,219.07 MA2.B
N$22
  Top 0.381: T22.3 135.25,223.52 135.89,222.88 135.89,219.07 MA3.B
N$23
  Top 0.381: T23.3 150.5,222.88 150.5,219.07 MA4.B
N$24
  Top 0.381: T24.3 163.83,223.52 164.47,222.88 164.47,219.07 MA5.B
N$25
  Top 0.381: T25.3 198.75,56.52 198.75,60.33 MA6.B
N$26
  Top 0.381: T26.3 185.42,55.88 184.78,56.52 184.78,60.33 MA7.B
N$27
  Top 0.381: T27.3 170.18,56.52 170.18,60.33 MA8.B
N$28
  Top 0.381: T28.3 156.84,55.88 156.21,56.52 156.21,60.33 MA9.B
N$29
  Top 0.381: T29.3 141.6,56.52 141.6,60.33 MA10.B
N$30
  Top 0.381: T30.3 128.27,55.88 127.64,56.52 127.64,60.33 MA11.B
N$31
  Top 0.381: T31.3 93.34,200.66 93.34,196.85 MB0.B
N$32
  Top 0.381: T32.3 106.68,201.29 107.31,200.66 107.31,196.85 MB1.B
N$33
  Top 0.381: T33.3 121.92,200.66 121.92,196.85 MB2.B
N$34
  Top 0.381: T34.3 135.25,201.29 135.89,200.66 135.89,196.85 MB3.B
N$35
  Top 0.381: T35.3 150.5,200.66 150.5,196.85 MB4.B
N$36
  Top 0.381: T36.3 163.83,201.29 164.47,200.66 164.47,196.85 MB5.B
N$37
  Top 0.381: T37.3 198.75,78.74 198.75,82.55 MB6.B
N$38
  Top 0.381: T38.3 185.42,81.92 MB7.B
N$39
  Bottom 0.381: T39.3 170.18,78.74 170.18,82.55 MB8.B
N$40
  Top 0.381: T40.3 156.84,78.11 156.21,78.74 156.21,82.55 MB9.B
N$41
  Top 0.381: T41.3 141.6,78.74 141.6,82.55 MB10.B
N$42
  Top 0.381: T42.3 128.27,78.11 127.64,78.74 127.64,82.55 MB11.B
N$43
  Top 0.381: T43.3 93.34,178.44 93.34,174.62 AC0.B
N$44
  Top 0.381: T44.3 106.68,179.07 107.31,178.44 107.31,174.62 AC1.B
N$45
  Bottom 0.381: T45.3 121.92,178.44 121.92,174.62 AC2.B
N$46
  Top 0.381: T46.3 135.25,179.07 135.89,178.44 135.89,174.62 AC3.B
N$47
  Top 0.381: T47.3 150.5,178.44 150.5,174.62 AC4.B
N$48
  Top 0.381: T48.3 163.83,179.07 164.47,178.44 164.47,174.62 AC5.B
N$49
  Top 0.381: T49.3 198.75,100.97 198.75,104.78 AC6.B
N$50
  Top 0.381: T50.3 185.42,100.33 184.78,100.97 184.78,104.78 AC7.B
N$51
  Top 0.381: T51.3 170.18,100.97 170.18,104.78 AC8.B
N$52
  Top 0.381: T52.3 156.84,100.33 156.21,100.97 156.21,104.78 AC9.B
N$53
  Bottom 0.381: T53.3 141.6,100.97 141.6,104.78 AC10.B
N$54
  Top 0.381: T54.3 127.64,102.23 127.64,104.78 AC11.B
N$55
  Top 0.381: T55.3 92.71,158.75 93.34,158.12 93.34,153.67 MQ0.B
N$56
  Top 0.381: T56.3 106.68,158.12 107.31,157.48 107.31,153.67 MQ1.B
N$57
  Top 0.381: T57.3 121.28,158.75 121.92,158.12 121.92,153.67 MQ2.B
N$58
  Top 0.381: T58.3 135.25,158.12 135.89,157.48 135.89,153.67 MQ3.B
N$59
  Top 0.381: T59.3 149.86,158.75 150.5,158.12 150.5,153.67 MQ4.B
N$60
  Bottom 0.381: T60.3 163.83,158.12 164.47,157.48 164.47,153.67 MQ5.B
N$61
  Top 0.381: T61.3 199.39,120.65 198.75,121.28 198.75,125.73 MQ6.B
N$62
  Bottom 0.381: T62.3 185.42,121.28 184.78,121.92 184.78,125.73 MQ7.B
N$63
  Top 0.381: T63.3 170.81,120.65 170.18,121.28 170.18,125.73 MQ8.B
N$64
  Top 0.381: T64.3 156.84,121.28 156.21,121.92 156.21,125.73 MQ9.B
N$65
  Top 0.381: T65.3 142.24,120.65 141.6,121.28 141.6,125.73 MQ10.B
N$66
  Top 0.381: T66.3 128.27,121.28 127.64,121.92 127.64,125.73 MQ11.B
N$67
  Top 0.381: T67.3 5.08,158.12 5.71,157.48 5.71,153.67 SC0.B
N$68
  Top 0.381: T68.3 19.68,158.75 20.32,158.12 20.32,153.67 SC1.B
N$69
  Bottom 0.381: T69.3 33.66,158.12 34.29,157.48 34.29,153.67 SC2.B
N$70
  Bottom 0.381: T70.3 48.26,158.75 48.9,158.12 48.9,153.67 SC3.B
N$71
  Bottom 0.381: T71.3 62.23,158.12 62.87,157.48 62.87,153.67 SC4.B
N$72
  Top 0.381: T72.3 78.11,179.07 78.74,178.44 78.74,174.62 LINK.B
N$73
  Bottom 0.381: T73.3 20.32,40.64 14.61,40.64 ION.B
N$74
  Bottom 0.381: T74.3 14.61,52.07 14.61,51.44 13.34,50.16 PAUSE.B
N$75
  Top 0.381: T75.3 20.32,62.87 14.61,62.87 RUN.B
N$76
  Bottom 0.381: T76.3 33.66,38.73 FETCH.B
N$77
  Bottom 0.381: T77.3 40.64,49.53 EXECUTE.B
N$78
  Top 0.381: T78.3 33.66,60.96 DEFER.B
N$79
  Bottom 0.381: T79.3 40.64,71.75 WORDCOUNT.B
N$80
  Bottom 0.381: T80.3 33.66,83.19 CURRENTADDRESS.B
N$81
  Bottom 0.381: T81.3 40.64,93.98 BREAK.B
N$82
  Top 0.381: T82.3 62.23,38.73 AND.B
N$83
  Bottom 0.381: T83.3 69.22,49.53 TAD.B
N$84
  Bottom 0.381: T84.3 62.23,60.96 ISZ.B
N$85
  Bottom 0.381: T85.3 69.22,71.75 DCA.B
N$86
  Bottom 0.381: T86.3 62.23,83.19 JMS.B
N$87
  Bottom 0.381: T87.3 69.22,93.98 JMP.B
N$88
  Bottom 0.381: T88.3 62.23,105.41 IOT.B
N$89
  Bottom 0.381: T89.3 69.22,116.2 OPR.B
OPR
  Top 0.381: T89.2 59.69,117.47 48.26,106.05 48.26,26.67 49.53,25.4 D40.16 49.53,24.77 48.9,24.13 48.9,19.05 47.62,17.78 F40BOT.11
PAUSE
  Bottom 0.381: 33.02,20.95 33.66,21.59 33.66,27.94 20.95,27.94 10.79,38.1 10.79,41.91 15.24,46.35 15.24,50.8 T74.2 | 33.02,20.95 30.48,20.95 30.48,22.23 D40.31 | 33.02,20.95 34.92,20.95 37.47,18.41 37.47,17.78 38.1,17.14 F40TOP.17
PC0
  Top 0.381: T7.2 102.23,256.54 106.05,256.54 E40.1
  Bottom 0.381: D40TOP.1 114.3,262.25 107.31,262.25 107.31,257.18 E40.1
PC1
  Top 0.381: T8.2 107.95,248.28 116.2,248.28 116.2,254 E40.10 117.47,254.63 118.11,255.27 118.11,257.81 120.02,259.71 120.02,261.62 120.65,262.25 D40BOT.5
PC2
  Bottom 0.381: 120.65,257.81 120.02,257.18 E40.11 | 120.65,257.81 121.92,259.08 121.92,262.25 D40TOP.6 | 120.65,257.81 120.65,249.56 T9.2
PC3
  Top 0.381: T10.2 136.53,248.28 135.25,249.56 135.25,254 E40.24 133.99,254.63 133.35,255.27 133.35,257.81 134.62,259.08 134.62,262.25 D40BOT.14
PC4
  Bottom 0.381: T11.2 151.13,247.65 153.67,247.65 153.67,233.68 154.94,232.41 154.94,201.93 153.03,200.03 140.97,200.03 140.97,250.82 138.43,253.37 138.43,255.91 137.79,256.54 E40.25 136.53,257.18 135.25,258.44 135.25,262.25 D40TOP.14
PC5
  Top 0.381: 148.59,254 147.96,254 E40.34 | 148.59,254 149.86,254 155.57,248.28 165.1,248.28 T12.2 | 148.59,254 148.59,262.25 142.88,262.25 D40BOT.19
PC6
  Bottom 0.381: T13.2 198.12,31.11 187.32,31.11 187.32,27.3 182.88,22.86 F40.1 181.61,22.23 181.61,20.95 177.8,17.14 E40TOP.1
PC7
  Top 0.381: 173.35,26.04 172.72,25.4 F40.10 | 173.35,26.04 173.99,26.67 173.99,31.11 184.15,31.11 T14.2 | 173.35,26.04 173.35,21.59 172.09,20.32 172.09,17.78 171.45,17.14 E40BOT.5
PC8
  Bottom 0.381: T15.2 168.28,29.84 168.28,23.5 168.91,22.86 F40.11 170.18,22.23 170.18,17.14 E40TOP.6
PC9
  Top 0.381: 155.57,31.11 154.94,30.48 154.94,25.4 F40.24 | 155.57,31.11 155.57,21.59 156.84,20.32 156.84,17.14 E40BOT.14 | 155.57,31.11 T16.2
PC10
  Bottom 0.381: T17.2 141.6,31.11 150.5,31.11 150.5,23.5 151.13,22.86 F40.25 152.4,22.23 156.84,17.78 156.84,17.14 E40TOP.14
PC11
  Top 0.381: 140.34,26.04 140.97,25.4 F40.34 | 140.34,26.04 136.53,29.84 136.53,31.11 127,31.11 T18.2 | 140.34,26.04 140.34,17.14 149.22,17.14 E40BOT.19
RUN
  Top 0.381: T75.2 27.3,57.15 27.3,36.2 28.57,34.92 28.57,23.5 27.94,22.86 D40.33
  Bottom 0.381: F40TOP.18 36.2,17.14 36.2,17.78 34.29,19.68 27.94,19.68 27.94,22.23 D40.33
SC0
  Bottom 0.381: 36.83,259.71 34.92,261.62 C40TOP.5 | 36.83,259.71 38.1,258.44 38.1,253.37 33.66,248.92 33.66,188.59 6.35,161.29 T67.2 | 36.83,259.71 36.83,259.08 34.92,257.18 C40.9
SC1
  Top 0.381: 22.86,252.09 23.5,252.09 23.5,254 C40.2 | 22.86,252.09 9.53,252.09 5.08,247.65 5.08,175.9 20.32,160.66 T68.2 | 22.86,252.09 22.86,262.25 28.57,262.25 C40BOT.1
SC2
  Top 0.381: T69.2 34.92,161.29 53.34,179.71 53.34,255.91 52.7,256.54 C40.23
  Bottom 0.381: C40TOP.13 47.62,262.25 48.26,261.62 48.26,260.35 51.44,257.18 C40.23
SC3
  Top 0.381: C40BOT.6 36.83,262.25 36.83,259.08 38.1,257.81 38.1,255.27 37.47,254.63 C40.12
  Bottom 0.381: T70.2 37.47,160.66 37.47,150.5 36.2,149.22 3.81,149.22 3.81,217.17 32.38,245.75 32.38,250.19 36.2,254 C40.12
SC4
  Bottom 0.381: 55.88,258.44 55.88,262.25 C40TOP.18 | 55.88,258.44 55.88,252.73 53.34,252.73 48.26,247.65 48.26,176.53 63.5,161.29 T71.2 | 55.88,258.44 62.87,258.44 64.14,257.18 C40.33
TAD
  Top 0.381: F40BOT.2 62.23,17.14 62.23,17.78 65.41,20.95 66.67,20.95 66.67,24.13 66.04,24.77 D40.4
  Bottom 0.381: T83.2 59.69,50.8 58.42,49.53 58.42,26.67 59.05,26.04 59.05,21.59 59.69,20.95 64.14,20.95 64.14,24.13 64.77,24.77 D40.4
WC
  Top 0.381: F40BOT.17 38.1,17.14 37.47,17.78 37.47,18.41 34.92,20.95 33.66,20.95 33.66,24.13 33.02,24.77 D40.30
  Bottom 0.381: T79.2 34.92,73.03 34.92,74.93 33.66,76.2 9.53,76.2 9.53,38.1 20.95,26.67 31.75,26.67 31.75,25.4 D40.30

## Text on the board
Bottom: 5404519 | PDP-8/I Light Board 50045108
